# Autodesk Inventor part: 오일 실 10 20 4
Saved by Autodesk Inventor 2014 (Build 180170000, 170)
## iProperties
Created: 2025-02
Part Number: 오일 실 10 20 4
Material: 고무
Document SubType Name: Modeling
Designer: dg
Density: 0.93 g/cm^3
Appearance: 고무 - 검은색 - 버전 1.1
Mass: 0.55557 g
Surface Area: 9.8248 cm^2
Volume: 0.597387 cm^3
Author: jhkim
Description: 오일 실 - 비스프링, 조립 GA
Creation Date: 2025-01-06
Sending System: Autodesk Inventor 2025
Preprocessor: ST-DEVELOPER v20
Author: dg
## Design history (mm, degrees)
node "오일 실 10 20 41"
body "Solid1"
node "기준1"
